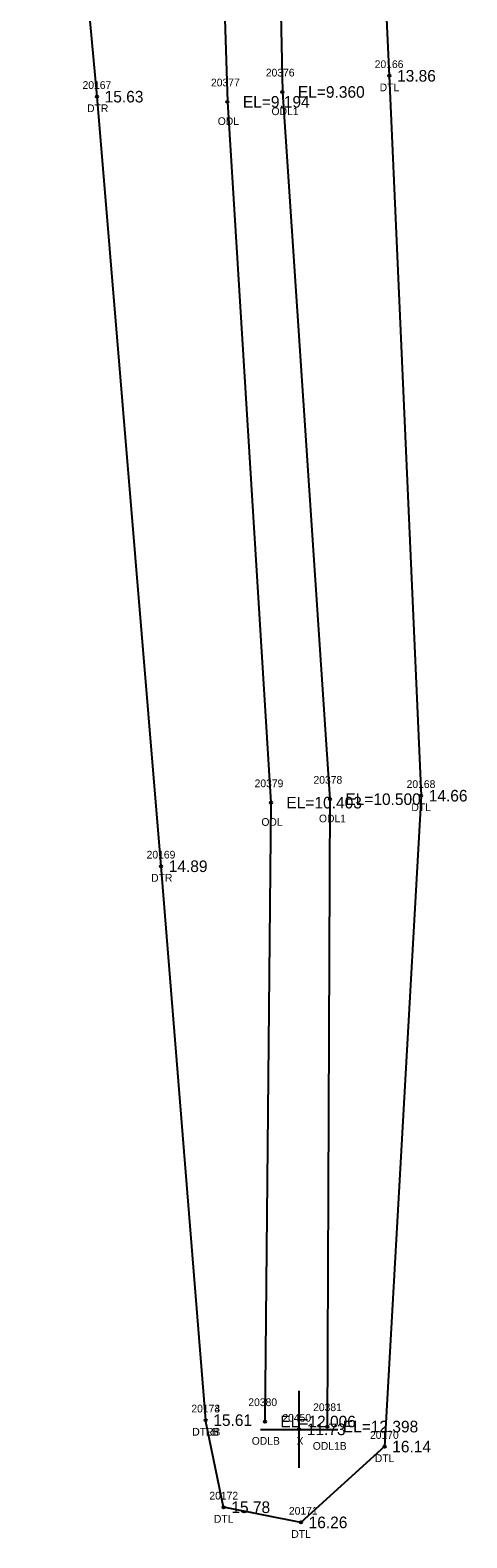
# Model space of a CAD drawing. Extents: x 2072302 to 2072980, y 127650 to 129736.
# Drawn here: x 2072393.7 to 2072450.2, y 127650.2 to 127845.3 of the extents above; entities that cross this region are included whole.
import ezdxf

# ---------------------------------------------------------------- set-up
doc = ezdxf.new("R2010")
doc.units = 0
for name, color, linetype in [('RD_EX_H2O', 7, 'Continuous'), ('RD_EX_H2O_txCode', 7, 'Continuous'), ('RD_EX_Misc', 7, 'Continuous'), ('RD_EX_Misc_txCode', 7, 'Continuous'), ('RD_EX_TX_H2O_ELEV', 7, 'Continuous'), ('RD_EX_TX_Misc_ELEV', 7, 'Continuous'), ('RD_SMD_Locator', 7, 'Continuous')]:
    doc.layers.add(name, color=color, linetype=linetype)

msp = doc.modelspace()

# ---------------------------------------------------------------- linework, layer by layer
at = {"layer": 'RD_EX_H2O'}
for points in [[(2072397.43, 128013.21), (2072408.15, 128037.05), (2072417.14, 128037.67), (2072426.18, 128028.89), (2072428.77, 128008.19), (2072436.1, 127925.95), (2072440.16, 127839.38), (2072444.26, 127746.21), (2072439.54, 127661.97), (2072428.72, 127652.16), (2072418.72, 127654.12), (2072416.39, 127665.39)], [(2072408.21, 128010.77), (2072414.25, 128030.85), (2072417.82, 128027.31), (2072412.85, 128005.56), (2072424.49, 127924.24), (2072426.33, 127837.29), (2072432.47, 127745.76), (2072432.14, 127664.56)], [(2072397.43, 128013.21), (2072393.69, 127930.01), (2072402.33, 127836.68), (2072410.62, 127737.08), (2072416.39, 127665.39)], [(2072408.21, 128010.77), (2072416.45, 127921.77), (2072419.21, 127836.01), (2072424.85, 127745.31), (2072424.07, 127665.21)]]:
    msp.add_lwpolyline(points, dxfattribs=at)
at = {"layer": 'RD_EX_Misc'}
for p, q in [((2072428.48, 127659.2), (2072428.48, 127669.2)), ((2072423.48, 127664.2), (2072433.48, 127664.2))]:
    msp.add_line(p, q, dxfattribs=at)
at = {"layer": 'RD_SMD_Locator'}
for centre in [(2072440.16, 127839.38), (2072402.33, 127836.68), (2072419.21, 127836.01), (2072426.33, 127837.29), (2072444.26, 127746.21), (2072424.85, 127745.31), (2072432.47, 127745.76), (2072410.62, 127737.08), (2072416.39, 127665.39), (2072416.39, 127665.39), (2072424.07, 127665.21), (2072428.48, 127664.2), (2072432.14, 127664.56), (2072439.54, 127661.97), (2072418.72, 127654.12), (2072428.72, 127652.16)]:
    msp.add_circle(centre, 0.15, dxfattribs=at)

# ---------------------------------------------------------------- texts
at = {"layer": 'RD_EX_H2O_txCode'}
for s, p in [('20376', (2072424.18, 127839.29)), ('20166', (2072438.27, 127840.38)), ('20167', (2072400.47, 127837.68)), ('20377', (2072417.09, 127838.01)), ('DTL', (2072438.91, 127837.38)), ('DTR', (2072401.06, 127834.68)), ('ODL', (2072417.96, 127833.01)), ('ODL1', (2072424.92, 127834.29)), ('20379', (2072422.73, 127747.31)), ('20378', (2072430.35, 127747.76)), ('20168', (2072442.4, 127747.21)), ('DTL', (2072443.01, 127744.21)), ('ODL', (2072423.61, 127742.31)), ('ODL1', (2072431.06, 127742.76)), ('20169', (2072408.76, 127738.08)), ('DTR', (2072409.35, 127735.08)), ('20380', (2072421.92, 127667.21)), ('20173', (2072414.55, 127666.39)), ('20174', (2072414.55, 127666.39)), ('20381', (2072430.3, 127666.56)), ('DTRB', (2072414.65, 127663.39)), ('DTLB', (2072414.67, 127663.39)), ('ODLB', (2072422.36, 127662.21)), ('ODL1B', (2072430.26, 127661.56)), ('20170', (2072437.66, 127662.97)), ('DTL', (2072438.29, 127659.97)), ('20172', (2072416.88, 127655.12)), ('DTL', (2072417.47, 127652.12)), ('20171', (2072427.17, 127653.16)), ('DTL', (2072427.48, 127650.16))]:
    msp.add_text(s, height=1, dxfattribs=at).set_placement(p)
at = {"layer": 'RD_EX_Misc_txCode'}
for s, p in [('20450', (2072426.32, 127665.2)), ('X', (2072428.16, 127662.2))]:
    msp.add_text(s, height=1, dxfattribs=at).set_placement(p)
at = {"layer": 'RD_EX_TX_H2O_ELEV'}
for s, p in [('13.86', (2072441.16, 127838.63)), ('EL=9.360', (2072428.33, 127836.54)), ('15.63', (2072403.33, 127835.93)), ('EL=9.194', (2072421.21, 127835.26)), ('EL=10.403', (2072426.85, 127744.56)), ('EL=10.500', (2072434.47, 127745.01)), ('14.66', (2072445.26, 127745.46)), ('14.89', (2072411.62, 127736.33)), ('15.61', (2072417.39, 127664.64)), ('15.61', (2072417.39, 127664.64)), ('EL=12.006', (2072426.07, 127664.46)), ('EL=12.398', (2072434.14, 127663.81)), ('16.14', (2072440.54, 127661.22)), ('15.78', (2072419.72, 127653.37)), ('16.26', (2072429.72, 127651.41))]:
    msp.add_text(s, height=1.5, dxfattribs=at).set_placement(p)
at = {"layer": 'RD_EX_TX_Misc_ELEV'}
msp.add_text('11.73', height=1.5, dxfattribs=at).set_placement((2072429.48, 127663.45))

doc.saveas('drawing.dxf')
